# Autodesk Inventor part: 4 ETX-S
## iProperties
Shininess: 27.0
Length Units: 11272
Angle Units: 11279
Time Units: 11290
Mass Units: 11286
Length Display Precision: 3
Angle Display Precision: 2
Category: Hydraulics
Created: 2001-03
Part Number: 4 ETX-S
Material: Stainless Steel, Austenitic
Catalog Web Link: http://www.aeroquip.com
Description: Parker Triple-Lok Union Elbow
Document SubType Name: Modeling
Designer: QBZ
Density: 7.86
Volumn: 11.938033425281926
Area: 60.34729061233818
PropertySet Name: Model Information
Control State: 0
Master: False
Checked Out: False
Last Check In By: Charles Bliss
Last Check In Date: 2003-09-27
Title: JIC Elbow 90 deg Union
Subject: Hydraulic Adapters
Author: QBZ
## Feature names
1. Body1 [Extrusion]
2. Body2 [Extrusion]
3. Revolution1
4. JIC 1 [Revolution]
5. JIC 2 [Revolution]
6. JIC1 id
7. JIC2 id [Hole]
8. Fillet1
